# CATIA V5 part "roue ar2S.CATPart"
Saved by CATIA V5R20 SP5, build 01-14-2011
Part number: roue ar2S
Publications: "Plan.1"
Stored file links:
  U:\think motion\fin\roue ar2S.CATPart
  U:\think motion\fin\squelette.CATProduct
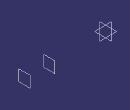
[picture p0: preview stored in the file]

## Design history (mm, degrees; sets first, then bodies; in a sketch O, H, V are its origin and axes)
Set1
  Plane1: linked copy from another document
Set2
  Plane2: type Offset, RefPlane Plane1, Offset 100, reversed
Body1 (main body)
